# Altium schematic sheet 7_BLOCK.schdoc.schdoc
size 302 x 215 mm; Symbol: Sheet_A4; Device: Sheet_A4; @Project Name: Avaota Pi A; Company: YuzukiHD; Version: 1.0; @Page No: 1; @Page Count: 13; @Update Date: 2024-02-19; Comment: GloomyGhost
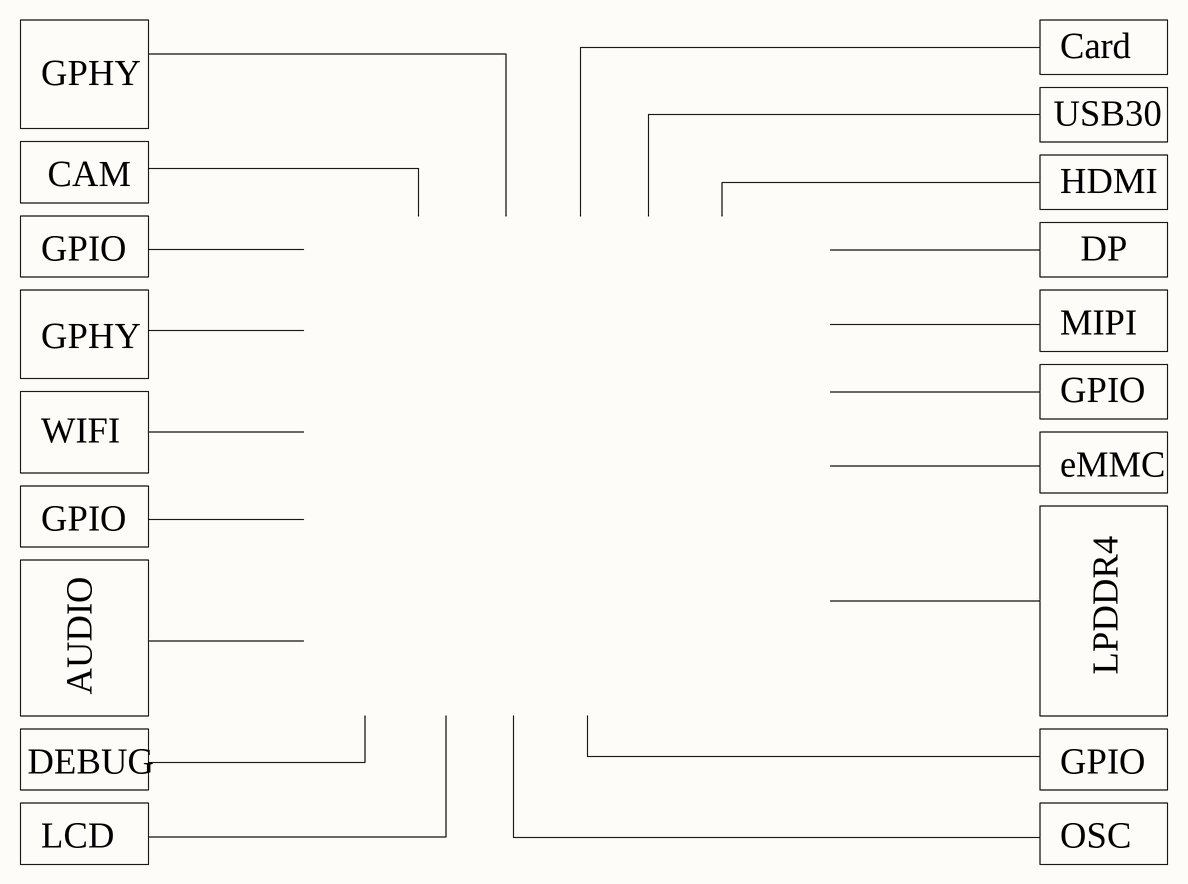
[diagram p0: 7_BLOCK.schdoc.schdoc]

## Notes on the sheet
- GPHY
- USB30
- Card
- CAM
- GPIO
- HDMI
- DP
- MIPI
- WIFI
- eMMC
- LPDDR4
- AUDIO
- DEBUG
- LCD
- OSC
